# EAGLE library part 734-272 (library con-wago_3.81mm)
Serie 734, Stiftleiste (für Leiterplatten) Einlötstift abgewinkelt 1 x 1 mm / Series 734, Male header (for PCBs) Angled solder pin 1 x 1 mm Polzahl / Pole No.: 12 Rastermaß / Pitch: 3.81 mm Bemessungsspannung / Rated Voltage: 160 V Nennstrom / Nominal Current: 10 A Lötstiftlänge: / Solder Pin Length: 3.8 mm Farbe / Color: orange / orange Stand: 01.01.2012. Die jeweils aktuellen Daten zu diesem Artikel finden Sie in unserem Produktkatalog, den Sie unter www.wago.com einsehen können. As of: 01/01/2012. Please find the newest data for this article in our product catalogue, which can be viewed under www.wago.com.
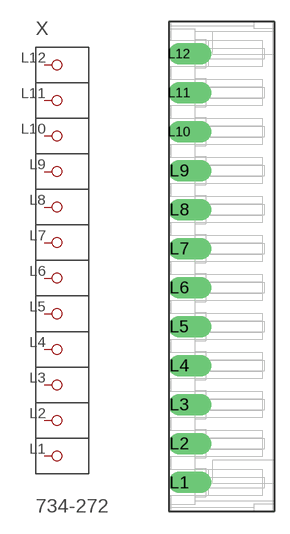
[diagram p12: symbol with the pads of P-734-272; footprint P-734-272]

Designator prefix X

## 734-272  [P-734-272]
L1  P1
L2  P2
L3  P3
L4  P4
L5  P5
L6  P6
L7  P7
L8  P8
L9  P9
L10  P10
L11  P11
L12  P12

## Footprint P-734-272 (pad centres in mm)
drill 1.4 pad 2 offset: L1 -4.15,-21.105; L2 -4.15,-17.295; L3 -4.15,-13.485; L4 -4.15,-9.675; L5 -4.15,-5.865; L6 -4.15,-2.055; L7 -4.15,1.755; L8 -4.15,5.565; L9 -4.15,9.375; L10 -4.15,13.185; L11 -4.15,16.995; L12 -4.15,20.805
